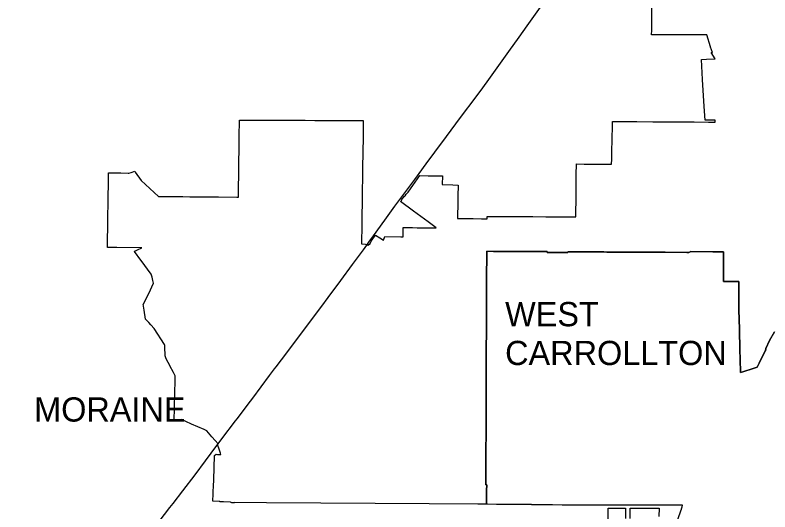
# Model space of a CAD drawing. Extents: x 0 to 34, y 0 to 22.
# Drawn here: x 4.6894 to 4.9396, y 14.6708 to 14.8356 of the extents above; entities that cross this region are included whole.
import ezdxf

# ---------------------------------------------------------------- set-up
doc = ezdxf.new("R2010")
doc.units = 0
for name, color, linetype in [('GM_X_Corporation', 7, 'Continuous'), ('GM_X_Corporation_Text', 7, 'Continuous'), ('GM_X_State_Route', 7, 'Continuous')]:
    doc.layers.add(name, color=color, linetype=linetype)

msp = doc.modelspace()

# ---------------------------------------------------------------- linework, layer by layer
at = {"layer": 'GM_X_Corporation'}
for points in [[(4.941067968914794, 14.730540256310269), (4.939395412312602, 14.727608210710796), (4.9382262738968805, 14.72496162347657), (4.938085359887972, 14.724252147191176), (4.938051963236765, 14.724185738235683), (4.936802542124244, 14.721701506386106), (4.936034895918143, 14.720175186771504), (4.9360298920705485, 14.720165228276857), (4.935564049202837, 14.719239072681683), (4.935468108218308, 14.719048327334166), (4.935460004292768, 14.719032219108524), (4.93532373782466, 14.718761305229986), (4.935029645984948, 14.71866699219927), (4.933990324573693, 14.718333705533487), (4.930644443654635, 14.717260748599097), (4.929806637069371, 14.716992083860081), (4.929804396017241, 14.717086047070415), (4.929780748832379, 14.718076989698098), (4.929725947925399, 14.720373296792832), (4.929683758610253, 14.722141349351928), (4.929642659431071, 14.723863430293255), (4.929597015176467, 14.725775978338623), (4.929494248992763, 14.73008229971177), (4.929479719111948, 14.730691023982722), (4.9293702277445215, 14.735279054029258), (4.929325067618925, 14.737171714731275), (4.9293155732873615, 14.737569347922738), (4.92927496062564, 14.739271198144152), (4.929264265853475, 14.739719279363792), (4.929291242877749, 14.74719848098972), (4.925829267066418, 14.747212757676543), (4.924211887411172, 14.747219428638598), (4.9242184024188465, 14.749194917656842), (4.924223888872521, 14.750860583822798), (4.924244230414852, 14.757034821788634), (4.9240749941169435, 14.757036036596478), (4.92339125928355, 14.757040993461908), (4.920683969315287, 14.757060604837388), (4.913299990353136, 14.757114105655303), (4.913155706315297, 14.75705938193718), (4.912944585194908, 14.756979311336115), (4.912673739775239, 14.756876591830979), (4.912351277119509, 14.756878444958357), (4.911988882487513, 14.756880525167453), (4.904876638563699, 14.75692142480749), (4.90131474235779, 14.756941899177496), (4.89990919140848, 14.756949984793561), (4.897579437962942, 14.756962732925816), (4.896856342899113, 14.756966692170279), (4.8943235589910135, 14.756980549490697), (4.892008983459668, 14.756993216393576), (4.889272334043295, 14.75698709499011), (4.8887897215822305, 14.756986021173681), (4.888532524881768, 14.75698544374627), (4.8864320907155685, 14.756987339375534), (4.885467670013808, 14.756993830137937), (4.884503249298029, 14.757000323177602), (4.883538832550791, 14.757006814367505), (4.882574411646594, 14.757013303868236), (4.881609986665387, 14.757019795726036), (4.880721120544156, 14.757025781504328), (4.880645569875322, 14.757026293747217), (4.879681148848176, 14.757032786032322), (4.878716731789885, 14.757039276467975), (4.877752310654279, 14.757045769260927), (4.8767878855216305, 14.757052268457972), (4.876418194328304, 14.757054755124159), (4.874810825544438, 14.757065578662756), (4.872598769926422, 14.7570804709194), (4.8725973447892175, 14.75683935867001), (4.871793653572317, 14.756843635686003), (4.869980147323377, 14.756853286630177), (4.869805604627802, 14.756854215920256), (4.868254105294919, 14.756862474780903), (4.868212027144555, 14.756862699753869), (4.866948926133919, 14.75686942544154), (4.865799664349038, 14.756875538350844), (4.865799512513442, 14.75711665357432), (4.864886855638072, 14.75712135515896), (4.862123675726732, 14.757135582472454), (4.860870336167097, 14.7571420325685), (4.854500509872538, 14.757174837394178), (4.851449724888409, 14.757190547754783), (4.847928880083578, 14.7572086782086), (4.845705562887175, 14.75722012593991), (4.845697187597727, 14.755296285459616), (4.845671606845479, 14.749417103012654), (4.845660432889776, 14.746848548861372), (4.845631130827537, 14.740115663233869), (4.845618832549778, 14.73728926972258), (4.845612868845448, 14.735919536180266), (4.845606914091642, 14.73455619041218), (4.84560610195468, 14.73437033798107), (4.845598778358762, 14.732696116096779), (4.845584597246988, 14.729464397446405), (4.845569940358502, 14.726123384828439), (4.845560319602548, 14.723930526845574), (4.845552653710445, 14.722183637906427), (4.845550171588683, 14.721571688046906), (4.845545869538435, 14.72051194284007), (4.845542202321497, 14.719610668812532), (4.845526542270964, 14.715754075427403), (4.845524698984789, 14.715050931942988), (4.845521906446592, 14.713979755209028), (4.845515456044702, 14.711511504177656), (4.845489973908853, 14.701756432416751), (4.845480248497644, 14.69803422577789), (4.845479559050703, 14.69776905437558), (4.8454010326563, 14.690268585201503), (4.845400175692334, 14.690186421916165), (4.845422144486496, 14.68602509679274), (4.845424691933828, 14.685542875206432), (4.845435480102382, 14.683498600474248), (4.845440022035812, 14.68263868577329), (4.845455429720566, 14.680576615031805), (4.8454616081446, 14.679750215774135), (4.845702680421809, 14.679748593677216), (4.8456896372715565, 14.677819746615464), (4.845676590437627, 14.675890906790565), (4.8456612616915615, 14.673623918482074), (4.845661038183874, 14.673590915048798), (4.8456609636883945, 14.673579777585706), (4.84566088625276, 14.673568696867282), (4.845660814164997, 14.673557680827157), (4.845659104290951, 14.673304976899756), (4.842727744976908, 14.673324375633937), (4.826653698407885, 14.673434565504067), (4.808693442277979, 14.673558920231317), (4.7906769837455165, 14.67368366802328), (4.772705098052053, 14.673808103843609), (4.76209482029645, 14.673881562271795), (4.7620824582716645, 14.673801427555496), (4.761274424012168, 14.673808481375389), (4.760738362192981, 14.673971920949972), (4.760738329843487, 14.673970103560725), (4.75850209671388, 14.674089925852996), (4.757296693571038, 14.67410958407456), (4.757298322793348, 14.674239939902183), (4.754930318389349, 14.674278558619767), (4.755036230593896, 14.676778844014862), (4.755051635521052, 14.677139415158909), (4.755076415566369, 14.677719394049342), (4.755095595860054, 14.678168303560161), (4.755115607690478, 14.678636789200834), (4.755125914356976, 14.678905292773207), (4.755141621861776, 14.679314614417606), (4.755223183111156, 14.681439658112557), (4.755531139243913, 14.6894631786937), (4.756073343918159, 14.689887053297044), (4.756473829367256, 14.689867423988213), (4.756820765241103, 14.689850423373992), (4.757430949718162, 14.689820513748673), (4.757603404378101, 14.689812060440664), (4.75746645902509, 14.69021254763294), (4.7568806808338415, 14.691928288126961), (4.756489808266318, 14.693068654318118), (4.756680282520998, 14.693322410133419), (4.755663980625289, 14.694512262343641), (4.7546572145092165, 14.695688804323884), (4.752921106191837, 14.697719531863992), (4.752014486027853, 14.698115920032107), (4.74787741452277, 14.699924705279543), (4.7460315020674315, 14.700731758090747), (4.745717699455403, 14.700868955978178), (4.745323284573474, 14.701041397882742), (4.744960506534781, 14.701200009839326), (4.744537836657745, 14.701384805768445), (4.744386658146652, 14.701353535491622), (4.742070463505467, 14.700874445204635), (4.7423336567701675, 14.710122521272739), (4.742356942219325, 14.710940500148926), (4.742366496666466, 14.711276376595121), (4.742380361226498, 14.711763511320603), (4.742410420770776, 14.712819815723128), (4.742493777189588, 14.715748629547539), (4.7424989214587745, 14.715929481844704), (4.741905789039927, 14.717035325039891), (4.740726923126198, 14.719233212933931), (4.740563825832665, 14.719537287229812), (4.739705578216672, 14.721137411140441), (4.7393147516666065, 14.72186607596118), (4.739088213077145, 14.722541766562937), (4.7390277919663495, 14.72548172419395), (4.739015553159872, 14.726077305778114), (4.738884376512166, 14.726284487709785), (4.735505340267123, 14.731621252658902), (4.73439927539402, 14.732794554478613), (4.73367800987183, 14.733559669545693), (4.732605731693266, 14.734697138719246), (4.732176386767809, 14.737661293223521), (4.7319795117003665, 14.739020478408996), (4.731969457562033, 14.739089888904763), (4.7319006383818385, 14.73956499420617), (4.732822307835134, 14.741482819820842), (4.734225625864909, 14.744402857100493), (4.73473242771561, 14.745457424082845), (4.7353162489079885, 14.746638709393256), (4.735057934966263, 14.747574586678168), (4.734775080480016, 14.74859940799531), (4.734482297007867, 14.749660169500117), (4.731177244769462, 14.75413371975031), (4.7311039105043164, 14.754232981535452), (4.728927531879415, 14.757178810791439), (4.728898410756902, 14.75721823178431), (4.72902606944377, 14.757277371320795), (4.729302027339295, 14.75740521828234), (4.7299567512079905, 14.757708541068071), (4.7300222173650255, 14.75773886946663), (4.731386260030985, 14.758370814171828), (4.723128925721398, 14.758441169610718), (4.721705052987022, 14.758453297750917), (4.720025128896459, 14.758467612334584), (4.72001804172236, 14.758854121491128), (4.720019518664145, 14.758949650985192), (4.720022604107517, 14.759148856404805), (4.7200254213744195, 14.759271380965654), (4.720024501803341, 14.759271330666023), (4.720145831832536, 14.76710760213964), (4.720179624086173, 14.76929029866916), (4.72023179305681, 14.772659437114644), (4.720262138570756, 14.774619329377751), (4.720277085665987, 14.775584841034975), (4.720334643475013, 14.779302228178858), (4.720355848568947, 14.780671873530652), (4.720375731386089, 14.781955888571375), (4.720379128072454, 14.782175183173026), (4.72039586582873, 14.78325643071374), (4.724494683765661, 14.783220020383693), (4.726899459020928, 14.78319713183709), (4.727131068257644, 14.783194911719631), (4.727814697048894, 14.783404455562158), (4.729047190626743, 14.78378223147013), (4.729239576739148, 14.783515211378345), (4.731236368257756, 14.780743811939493), (4.736974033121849, 14.775424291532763), (4.7373126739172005, 14.775421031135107), (4.739989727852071, 14.775395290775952), (4.743854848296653, 14.775358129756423), (4.744979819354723, 14.775355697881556), (4.747365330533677, 14.77535055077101), (4.749624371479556, 14.77534567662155), (4.753526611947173, 14.77533726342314), (4.756101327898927, 14.775331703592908), (4.756794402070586, 14.775324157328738), (4.7628596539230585, 14.775234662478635), (4.763406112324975, 14.77522659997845), (4.76340863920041, 14.775437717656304), (4.763436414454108, 14.777758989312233), (4.7634450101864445, 14.778477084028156), (4.763451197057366, 14.778831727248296), (4.763511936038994, 14.782314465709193), (4.763571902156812, 14.785752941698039), (4.7635843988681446, 14.78656309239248), (4.76365802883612, 14.791337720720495), (4.763702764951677, 14.794238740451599), (4.763717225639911, 14.795177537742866), (4.763800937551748, 14.80077763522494), (4.764031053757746, 14.800777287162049), (4.764961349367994, 14.800775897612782), (4.770103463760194, 14.80076818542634), (4.772533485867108, 14.800764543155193), (4.776597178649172, 14.800758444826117), (4.778749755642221, 14.80075521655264), (4.785547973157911, 14.800695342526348), (4.788771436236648, 14.800666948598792), (4.791248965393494, 14.800645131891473), (4.795448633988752, 14.800608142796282), (4.796914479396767, 14.800595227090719), (4.80196430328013, 14.800644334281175), (4.804304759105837, 14.800667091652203), (4.8048067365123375, 14.800671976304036), (4.804767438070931, 14.797947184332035), (4.804736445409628, 14.795798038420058), (4.804730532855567, 14.795388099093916), (4.804650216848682, 14.789818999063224), (4.804584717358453, 14.785277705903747), (4.804417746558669, 14.773699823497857), (4.804396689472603, 14.77223963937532), (4.804369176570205, 14.770331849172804), (4.804339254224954, 14.768256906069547), (4.804309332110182, 14.76618196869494), (4.804293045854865, 14.765052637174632), (4.804290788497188, 14.764896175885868), (4.804271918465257, 14.76358788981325), (4.804252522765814, 14.76224262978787), (4.804216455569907, 14.759741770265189), (4.805513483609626, 14.759586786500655), (4.80606133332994, 14.759521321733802), (4.806456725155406, 14.759245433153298), (4.807097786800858, 14.759858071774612), (4.8074251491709, 14.76058548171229), (4.808837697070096, 14.762540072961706), (4.810283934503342, 14.761681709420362), (4.811513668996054, 14.760952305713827), (4.811976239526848, 14.762112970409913), (4.817191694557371, 14.76206253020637), (4.817785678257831, 14.762056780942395), (4.817995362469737, 14.762054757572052), (4.81800646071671, 14.762583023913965), (4.81805932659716, 14.765100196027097), (4.819583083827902, 14.765086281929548), (4.820721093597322, 14.765075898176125), (4.821106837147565, 14.765072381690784), (4.8226305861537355, 14.765058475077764), (4.824068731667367, 14.765045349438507), (4.824154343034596, 14.765044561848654), (4.824916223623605, 14.765037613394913), (4.825678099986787, 14.765030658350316), (4.826107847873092, 14.765026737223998), (4.826829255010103, 14.765020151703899), (4.827201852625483, 14.765016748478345), (4.8289033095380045, 14.765001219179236), (4.826277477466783, 14.76695113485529), (4.821491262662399, 14.770505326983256), (4.817187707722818, 14.773701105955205), (4.817568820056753, 14.77421902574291), (4.817504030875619, 14.774267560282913), (4.818456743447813, 14.775562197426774), (4.818521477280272, 14.775514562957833), (4.818630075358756, 14.775662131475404), (4.818997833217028, 14.776161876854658), (4.819424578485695, 14.776577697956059), (4.819703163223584, 14.776849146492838), (4.823548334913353, 14.782345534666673), (4.826345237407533, 14.782312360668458), (4.829356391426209, 14.782276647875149), (4.830216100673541, 14.782266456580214), (4.831051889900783, 14.782256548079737), (4.830977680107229, 14.77935178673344), (4.834442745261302, 14.779254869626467), (4.836247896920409, 14.779204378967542), (4.836170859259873, 14.775508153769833), (4.83609382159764, 14.771811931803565), (4.836058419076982, 14.770150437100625), (4.836015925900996, 14.768156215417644), (4.836911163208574, 14.768143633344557), (4.837099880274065, 14.768140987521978), (4.841235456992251, 14.768082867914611), (4.843956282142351, 14.768044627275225), (4.84523829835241, 14.768026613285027), (4.8458811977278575, 14.768017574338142), (4.8458941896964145, 14.768807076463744), (4.847925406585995, 14.7687954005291), (4.850489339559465, 14.768780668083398), (4.851124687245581, 14.768777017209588), (4.853611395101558, 14.768762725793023), (4.855437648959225, 14.768752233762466), (4.856502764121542, 14.768746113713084), (4.860383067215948, 14.768723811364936), (4.861040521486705, 14.768720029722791), (4.865326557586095, 14.76869540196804), (4.866327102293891, 14.768689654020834), (4.87026715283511, 14.768667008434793), (4.871346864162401, 14.768660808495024), (4.875244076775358, 14.7686384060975), (4.87527017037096, 14.77054460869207), (4.875322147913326, 14.77393711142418), (4.87533256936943, 14.774617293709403), (4.875325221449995, 14.776126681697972), (4.875320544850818, 14.777087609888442), (4.875313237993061, 14.778587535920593), (4.875383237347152, 14.782621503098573), (4.875445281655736, 14.786197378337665), (4.878064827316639, 14.78618269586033), (4.878940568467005, 14.786177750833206), (4.880503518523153, 14.786168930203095), (4.880578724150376, 14.786168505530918), (4.882294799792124, 14.786158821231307), (4.8843418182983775, 14.786147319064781), (4.887116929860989, 14.786131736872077), (4.887147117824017, 14.787791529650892), (4.887177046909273, 14.789436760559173), (4.887221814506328, 14.791898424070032), (4.8872373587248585, 14.792753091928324), (4.887253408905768, 14.793635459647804), (4.8873622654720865, 14.799620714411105), (4.887377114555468, 14.800321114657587), (4.888699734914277, 14.800314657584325), (4.889061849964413, 14.800312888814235), (4.889177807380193, 14.800312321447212), (4.893642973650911, 14.800268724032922), (4.895411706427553, 14.800251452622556), (4.900742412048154, 14.800201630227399), (4.901086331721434, 14.800199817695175), (4.906641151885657, 14.80017054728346), (4.909370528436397, 14.800156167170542), (4.910367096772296, 14.800150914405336), (4.9119320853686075, 14.800142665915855), (4.914482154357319, 14.800129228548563), (4.919249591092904, 14.800104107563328), (4.921417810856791, 14.800092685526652), (4.92146754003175, 14.800092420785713), (4.921453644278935, 14.800403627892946), (4.921436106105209, 14.800735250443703), (4.921400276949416, 14.800735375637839), (4.919725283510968, 14.800741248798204), (4.918211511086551, 14.800746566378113), (4.918070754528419, 14.8007470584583), (4.917808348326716, 14.805236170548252), (4.917283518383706, 14.814214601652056), (4.9168925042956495, 14.820903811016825), (4.916951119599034, 14.820905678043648), (4.918609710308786, 14.820958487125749), (4.921469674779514, 14.821049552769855), (4.9201315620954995, 14.823209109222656), (4.920510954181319, 14.823140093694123), (4.919919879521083, 14.824995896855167), (4.919905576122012, 14.825040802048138), (4.918665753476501, 14.829055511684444), (4.914678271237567, 14.829061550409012), (4.912061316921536, 14.82906550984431), (4.9111939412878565, 14.829066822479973), (4.905186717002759, 14.829075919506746), (4.904701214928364, 14.829076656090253), (4.9008445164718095, 14.829082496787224), (4.900362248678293, 14.829083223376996), (4.900384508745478, 14.830581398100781), (4.900429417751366, 14.83360407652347), (4.9004506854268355, 14.835035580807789), (4.900562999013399, 14.84259491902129)], [(4.908853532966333, 14.667699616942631), (4.910325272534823, 14.672017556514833), (4.910322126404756, 14.672017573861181), (4.910407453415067, 14.67225866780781), (4.910437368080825, 14.672346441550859), (4.91048940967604, 14.672499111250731), (4.9106535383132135, 14.672980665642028), (4.9101927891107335, 14.672982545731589), (4.907905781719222, 14.672991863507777), (4.901707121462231, 14.672976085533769), (4.9000936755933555, 14.672971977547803), (4.8944428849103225, 14.67295759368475), (4.892940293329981, 14.672953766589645), (4.892805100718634, 14.672954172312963), (4.885148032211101, 14.672977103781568), (4.883379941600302, 14.67298239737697), (4.881611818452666, 14.67299202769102), (4.870722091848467, 14.673054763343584), (4.867482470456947, 14.673076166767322), (4.865579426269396, 14.673088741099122), (4.865155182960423, 14.67309154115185), (4.861834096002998, 14.673113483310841), (4.860590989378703, 14.673121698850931), (4.860591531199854, 14.673202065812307), (4.858984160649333, 14.673212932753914), (4.857376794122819, 14.673223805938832), (4.855769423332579, 14.673234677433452), (4.854162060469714, 14.673245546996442), (4.852554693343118, 14.673256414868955), (4.850947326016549, 14.673267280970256), (4.84893811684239, 14.673280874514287), (4.845946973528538, 14.673302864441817), (4.845659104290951, 14.673304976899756), (4.845660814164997, 14.673557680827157), (4.8456609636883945, 14.673579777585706), (4.845661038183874, 14.673590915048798), (4.845661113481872, 14.673602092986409), (4.845661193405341, 14.673613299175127), (4.845661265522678, 14.673624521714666), (4.845676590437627, 14.675890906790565), (4.8456896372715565, 14.677819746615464), (4.845702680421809, 14.679748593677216), (4.8454616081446, 14.679750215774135), (4.845455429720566, 14.680576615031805), (4.845440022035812, 14.68263868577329), (4.845435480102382, 14.683498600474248), (4.845424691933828, 14.685542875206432), (4.845422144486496, 14.68602509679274), (4.845400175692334, 14.690186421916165), (4.8454010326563, 14.690268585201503), (4.845479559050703, 14.69776905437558), (4.845480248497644, 14.69803422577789), (4.845489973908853, 14.701756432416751), (4.845490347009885, 14.701900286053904), (4.845515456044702, 14.711511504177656), (4.845521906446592, 14.713979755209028), (4.845524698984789, 14.715050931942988), (4.845526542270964, 14.715754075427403), (4.845542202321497, 14.719610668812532), (4.845545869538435, 14.72051194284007), (4.845550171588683, 14.721571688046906), (4.845552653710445, 14.722183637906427), (4.845560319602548, 14.723930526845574), (4.845569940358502, 14.726123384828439), (4.845584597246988, 14.729464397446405), (4.845597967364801, 14.732510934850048), (4.845598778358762, 14.732696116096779), (4.84560610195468, 14.73437033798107), (4.845606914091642, 14.73455619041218), (4.84561286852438, 14.735919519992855), (4.8456184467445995, 14.737200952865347), (4.845618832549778, 14.73728926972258), (4.845631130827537, 14.740115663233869), (4.845660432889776, 14.746848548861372), (4.845671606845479, 14.749417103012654), (4.845697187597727, 14.755296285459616), (4.845705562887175, 14.75722012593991), (4.847928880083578, 14.7572086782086), (4.851449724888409, 14.757190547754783), (4.854500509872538, 14.757174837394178), (4.860870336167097, 14.7571420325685), (4.862124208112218, 14.757135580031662), (4.864886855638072, 14.75712135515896), (4.865799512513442, 14.75711665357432), (4.865799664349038, 14.756875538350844), (4.866948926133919, 14.75686942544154), (4.868212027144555, 14.756862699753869), (4.869805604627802, 14.756854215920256), (4.869980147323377, 14.756853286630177), (4.871793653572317, 14.756843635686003), (4.8725973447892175, 14.75683935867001), (4.872598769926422, 14.7570804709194), (4.874810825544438, 14.757065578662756), (4.876418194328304, 14.757054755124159), (4.8767878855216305, 14.757052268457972), (4.877752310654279, 14.757045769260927), (4.878716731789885, 14.757039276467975), (4.879681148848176, 14.757032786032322), (4.880645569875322, 14.757026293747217), (4.881609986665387, 14.757019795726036), (4.882574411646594, 14.757013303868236), (4.883538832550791, 14.757006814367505), (4.884503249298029, 14.757000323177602), (4.885467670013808, 14.756993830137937), (4.8864320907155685, 14.756987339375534), (4.888532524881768, 14.75698544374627), (4.8887897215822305, 14.756986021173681), (4.889272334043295, 14.75698709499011), (4.892008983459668, 14.756993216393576), (4.8943235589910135, 14.756980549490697), (4.896856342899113, 14.756966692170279), (4.897579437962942, 14.756962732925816), (4.89990919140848, 14.756949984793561), (4.90131474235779, 14.756941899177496), (4.904876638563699, 14.75692142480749), (4.911988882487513, 14.756880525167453), (4.912351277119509, 14.756878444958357), (4.912673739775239, 14.756876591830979), (4.912944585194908, 14.756979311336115), (4.913155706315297, 14.75705938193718), (4.913299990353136, 14.757114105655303), (4.920683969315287, 14.757060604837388), (4.92339125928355, 14.757040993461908), (4.9240749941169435, 14.757036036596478), (4.924244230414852, 14.757034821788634), (4.924223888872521, 14.750860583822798), (4.9242184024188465, 14.749194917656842), (4.924211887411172, 14.747219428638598), (4.925829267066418, 14.747212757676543), (4.929291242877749, 14.74719848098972), (4.929264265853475, 14.739719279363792), (4.92927496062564, 14.739271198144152), (4.9293155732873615, 14.737569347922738), (4.929322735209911, 14.737269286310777), (4.929325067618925, 14.737171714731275), (4.9293702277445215, 14.735279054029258), (4.929479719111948, 14.730691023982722), (4.929494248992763, 14.73008229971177), (4.929597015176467, 14.725775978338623), (4.929642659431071, 14.723863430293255), (4.929683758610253, 14.722141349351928), (4.929725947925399, 14.720373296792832), (4.929780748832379, 14.718076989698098), (4.929804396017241, 14.717086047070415), (4.929806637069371, 14.716992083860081), (4.930644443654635, 14.717260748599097), (4.933990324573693, 14.718333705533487), (4.935029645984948, 14.71866699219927), (4.93532373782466, 14.718761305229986), (4.935460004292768, 14.719032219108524), (4.935468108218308, 14.719048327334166), (4.935564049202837, 14.719239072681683), (4.9360298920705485, 14.720165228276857), (4.936034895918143, 14.720175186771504), (4.936802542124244, 14.721701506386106), (4.938051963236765, 14.724185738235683), (4.938085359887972, 14.724252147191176), (4.9382262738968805, 14.72496162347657), (4.939395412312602, 14.727608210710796), (4.941067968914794, 14.730540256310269)], [(4.885951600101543, 14.66198984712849), (4.885989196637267, 14.67201013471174), (4.89120756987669, 14.671994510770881), (4.891696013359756, 14.671993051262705), (4.8916544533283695, 14.668576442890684)], [(4.893261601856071, 14.66855855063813), (4.893303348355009, 14.67199024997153), (4.894098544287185, 14.671992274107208), (4.900070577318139, 14.672007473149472), (4.901602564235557, 14.672011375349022), (4.902834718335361, 14.67201450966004), (4.902799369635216, 14.66919089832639)]]:
    msp.add_lwpolyline(points, dxfattribs=at)
at = {"layer": 'GM_X_State_Route'}
msp.add_line((4.80490805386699, 14.75775654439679), (4.80593466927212, 14.759227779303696), dxfattribs=at)
for points in [[(4.846374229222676, 14.814225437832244), (4.853058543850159, 14.823504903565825), (4.856466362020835, 14.828275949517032), (4.859144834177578, 14.83205502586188), (4.86185969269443, 14.835881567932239), (4.867108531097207, 14.843341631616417), (4.867620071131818, 14.844034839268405)], [(4.80593466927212, 14.759227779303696), (4.80669053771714, 14.760276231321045), (4.8081562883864, 14.762351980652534), (4.811908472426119, 14.767594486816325), (4.81530732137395, 14.77215775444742), (4.8195404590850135, 14.777933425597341), (4.821836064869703, 14.78104222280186), (4.82565100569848, 14.786231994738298), (4.828520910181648, 14.790094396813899), (4.832347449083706, 14.795307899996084), (4.83707103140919, 14.801661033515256), (4.842200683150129, 14.808461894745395), (4.844425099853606, 14.811403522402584), (4.846374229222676, 14.814225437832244)], [(4.7910453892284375, 14.738995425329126), (4.79318500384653, 14.741868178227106), (4.797334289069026, 14.74752413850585), (4.801256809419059, 14.752821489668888), (4.80490805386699, 14.75775654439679)], [(4.775424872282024, 14.71826461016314), (4.775893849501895, 14.718884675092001), (4.779421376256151, 14.723584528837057), (4.784372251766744, 14.730089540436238), (4.787397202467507, 14.73410751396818), (4.790637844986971, 14.738448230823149), (4.7910453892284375, 14.738995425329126)], [(4.7666137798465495, 14.7064850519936), (4.768145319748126, 14.708540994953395), (4.770907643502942, 14.71229581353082), (4.7737053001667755, 14.715991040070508), (4.775424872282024, 14.71826461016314)], [(4.762964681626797, 14.701641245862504), (4.766052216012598, 14.705731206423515), (4.7666137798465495, 14.7064850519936)], [(4.754419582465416, 14.69030014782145), (4.757920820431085, 14.69495719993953), (4.76244136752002, 14.700948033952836), (4.762964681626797, 14.701641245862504)], [(4.741791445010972, 14.673613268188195), (4.7449587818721, 14.677737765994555), (4.749060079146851, 14.683106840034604), (4.752528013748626, 14.687734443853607), (4.7543695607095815, 14.69023361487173), (4.754419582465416, 14.69030014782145)], [(4.67425216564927, 14.587510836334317), (4.677671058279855, 14.591664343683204), (4.690561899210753, 14.60719779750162), (4.692702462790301, 14.609696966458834), (4.69742604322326, 14.615400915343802), (4.700044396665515, 14.618617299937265), (4.7041340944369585, 14.623842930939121), (4.709024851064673, 14.63034794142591), (4.712863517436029, 14.63549025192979), (4.719141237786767, 14.643944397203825), (4.740733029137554, 14.672245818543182), (4.741791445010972, 14.673613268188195)]]:
    msp.add_lwpolyline(points, dxfattribs=at)

# ---------------------------------------------------------------- texts
at = {"layer": 'GM_X_Corporation_Text'}
for s, p in [('WEST', (4.851812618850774, 14.732362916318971)), ('CARROLLTON', (4.851812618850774, 14.719481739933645)), ('MORAINE', (4.695720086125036, 14.700736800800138))]:
    msp.add_text(s, height=0.008037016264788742, rotation=1.0000000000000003e-05, dxfattribs=at).set_placement(p)

doc.saveas('drawing.dxf')
